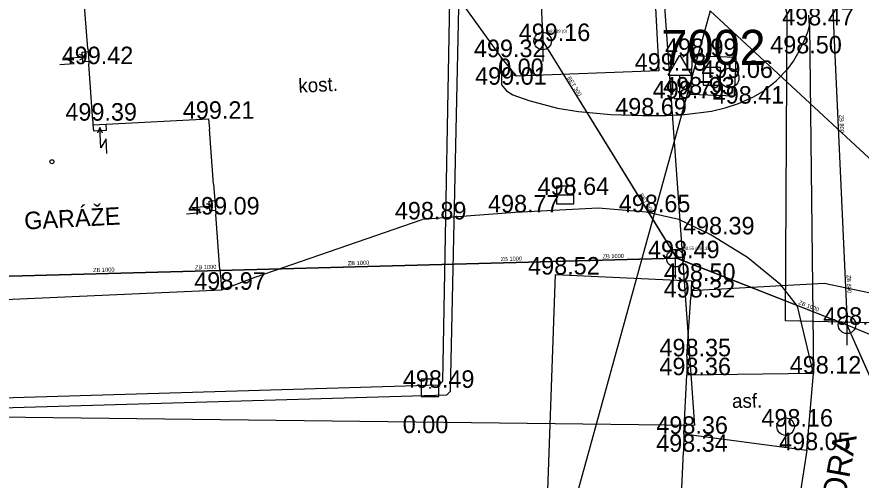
# Model space of a CAD drawing. Extents: x -669642 to -669119, y -1131006 to -1130466.
# Drawn here: x -669604.18 to -669567.99, y -1130599.43 to -1130579.6 of the extents above; entities that cross this region are included whole.
import ezdxf

# ---------------------------------------------------------------- set-up
doc = ezdxf.new("R2010")
doc.units = 0
for name, color, linetype in [('G_Bod_tecka', 7, 'Continuous'), ('G_Bod_vyska', 7, 'Continuous'), ('G_Bodove_pole', 7, 'Continuous'), ('G_Budovy-znacky', 7, 'Continuous'), ('G_Budovy_Objekty', 7, 'Continuous'), ('G_Budovy_vstupy', 7, 'Continuous'), ('G_Cesty_Schody', 7, 'Continuous'), ('G_Objekty_dopravni', 7, 'Continuous'), ('G_Plochy_zpevnene', 7, 'Continuous'), ('G_Popisy_Nazvy', 7, 'Continuous'), ('G_Popisy_objektu', 7, 'Continuous'), ('G_Popisy_povrchu', 7, 'Continuous'), ('G_Site-kanalizace', 7, 'Continuous'), ('G_Site-Rozvadece', 7, 'Continuous'), ('G_Site-Sachty_N', 7, 'Continuous'), ('G_Z_CHRANICKA-TEPLOVOD_kotovane', 7, 'Continuous'), ('G_Z_CHRANICKA-TEPLOVOD_zahozene', 7, 'Continuous'), ('G_Z_ELsilove_podz_kotovane', 7, 'Continuous'), ('G_Z_KANAL_podz_kotovane', 7, 'Continuous'), ('G_Z_SPOJE_nadz_kotovane', 7, 'Continuous'), ('Vrstva 10', 7, 'Continuous'), ('Vrstva 12', 7, 'Continuous'), ('Vrstva 13', 7, 'Continuous'), ('Vrstva 2', 7, 'Continuous'), ('Vrstva 3', 7, 'Continuous'), ('Vrstva 8', 7, 'Continuous')]:
    doc.layers.add(name, color=color, linetype=linetype)

msp = doc.modelspace()

# ---------------------------------------------------------------- linework, layer by layer
at = {"layer": 'G_Bod_tecka'}
for p, q in [((-669570.21, -1130579.96), (-669570.21, -1130579.96)), ((-669581.64, -1130580.63), (-669581.64, -1130580.63)), ((-669583.42, -1130581.32), (-669583.42, -1130581.32)), ((-669575.23, -1130581.27), (-669575.23, -1130581.27)), ((-669570.7, -1130581.16), (-669570.7, -1130581.16)), ((-669601.09, -1130581.62), (-669601.09, -1130581.62)), ((-669576.67, -1130581.9), (-669576.67, -1130581.9)), ((-669582.77, -1130582.13), (-669582.77, -1130582.13)), ((-669573.64, -1130582.21), (-669573.64, -1130582.21)), ((-669583.41, -1130582.5), (-669583.41, -1130582.5)), ((-669575.76, -1130583.09), (-669575.76, -1130583.09)), ((-669575.31, -1130582.92), (-669575.31, -1130582.92)), ((-669573.25, -1130583.31), (-669573.25, -1130583.31)), ((-669577.35, -1130583.82), (-669577.35, -1130583.82)), ((-669600.93, -1130584.04), (-669600.93, -1130584.04)), ((-669595.96, -1130583.96), (-669595.96, -1130583.96)), ((-669580.68, -1130587.22), (-669580.68, -1130587.22)), ((-669595.65, -1130588.06), (-669595.65, -1130588.06)), ((-669582.82, -1130587.97), (-669582.82, -1130587.97)), ((-669577.2, -1130587.96), (-669577.2, -1130587.96)), ((-669586.81, -1130588.27), (-669586.81, -1130588.27)), ((-669574.46, -1130588.91), (-669574.46, -1130588.91)), ((-669575.96, -1130589.93), (-669575.96, -1130589.93)), ((-669581.1, -1130590.63), (-669581.1, -1130590.63)), ((-669575.26, -1130590.9), (-669575.26, -1130590.9)), ((-669595.41, -1130591.28), (-669595.41, -1130591.28)), ((-669575.29, -1130591.61), (-669575.29, -1130591.61)), ((-669568.6, -1130592.78), (-669568.6, -1130592.78)), ((-669575.47, -1130594.13), (-669575.47, -1130594.13)), ((-669575.46, -1130594.94), (-669575.46, -1130594.94)), ((-669570.03, -1130594.87), (-669570.03, -1130594.87)), ((-669586.47, -1130595.48), (-669586.47, -1130595.48)), ((-669571.23, -1130597.14), (-669571.23, -1130597.14)), ((-669586.86, -1130597.42), (-669586.86, -1130597.42)), ((-669575.59, -1130597.45), (-669575.59, -1130597.45)), ((-669575.61, -1130598.22), (-669575.61, -1130598.22)), ((-669570.32, -1130598.15), (-669570.32, -1130598.15))]:
    msp.add_line(p, q, dxfattribs=at)
at = {"layer": 'G_Bodove_pole'}
for radius in [0.412, 0.05]:
    msp.add_circle((-669573.64, -1130582.21), radius, dxfattribs=at)
at = {"layer": 'G_Budovy-znacky'}
msp.add_circle((-669602.679, -1130585.8), 0.0875, dxfattribs=at)
at = {"layer": 'G_Budovy_Objekty'}
for p, q in [((-669601.14, -1130580.95), (-669601.13, -1130581.08)), ((-669601.13, -1130581.08), (-669601.1, -1130581.5)), ((-669601.1, -1130581.5), (-669601.09, -1130581.62)), ((-669600.93, -1130584.04), (-669600.92, -1130584.22)), ((-669600.92, -1130584.22), (-669600.35, -1130584.19)), ((-669600.35, -1130584.19), (-669595.96, -1130583.96)), ((-669595.96, -1130583.96), (-669595.93, -1130584.4)), ((-669595.75, -1130586.76), (-669595.7, -1130587.46)), ((-669595.7, -1130587.46), (-669595.66, -1130587.89)), ((-669595.66, -1130587.89), (-669595.65, -1130588.06)), ((-669595.48, -1130590.41), (-669595.44, -1130590.84)), ((-669581.1, -1130590.63), (-669581.86, -1130611.31)), ((-669581.1, -1130590.63), (-669575.26, -1130590.9)), ((-669595.44, -1130590.84), (-669595.41, -1130591.28)), ((-669575.26, -1130590.9), (-669575.29, -1130591.61)), ((-669606.39, -1130591.78), (-669595.41, -1130591.28)), ((-669575.47, -1130594.13), (-669575.46, -1130594.94)), ((-669575.59, -1130597.45), (-669575.61, -1130598.22))]:
    msp.add_line(p, q, dxfattribs=at)
at = {"layer": 'G_Budovy_vstupy'}
for p, q in [((-669601.14, -1130580.95), (-669601.33, -1130578.53)), ((-669600.93, -1130584.04), (-669601.09, -1130581.62)), ((-669595.75, -1130586.76), (-669595.93, -1130584.4)), ((-669595.48, -1130590.41), (-669595.65, -1130588.06))]:
    msp.add_line(p, q, dxfattribs=at)
for points in [[(-669575.47, -1130594.13), (-669575.29, -1130591.61)], [(-669575.59, -1130597.45), (-669575.46, -1130594.94)], [(-669575.72, -1130600.72), (-669575.61, -1130598.22)]]:
    msp.add_lwpolyline(points, dxfattribs=at)
at = {"layer": 'G_Cesty_Schody'}
for p, q in [((-669583.42, -1130581.32), (-669586.72, -1130576.72)), ((-669570.21, -1130579.96), (-669570.03, -1130594.87))]:
    msp.add_line(p, q, dxfattribs=at)
at = {"layer": 'G_Objekty_dopravni'}
for p, q in [((-669576.26, -1130582.09), (-669575.76, -1130581.24)), ((-669575.76, -1130581.24), (-669575.26, -1130582.09)), ((-669576.26, -1130582.09), (-669575.26, -1130582.09)), ((-669575.76, -1130583.09), (-669575.76, -1130582.09)), ((-669576.01, -1130583.09), (-669575.51, -1130583.09))]:
    msp.add_line(p, q, dxfattribs=at)
at = {"layer": 'G_Plochy_zpevnene'}
for p, q in [((-669582.77, -1130582.13), (-669583.42, -1130581.32)), ((-669575.23, -1130581.27), (-669575.31, -1130582.92)), ((-669573.36, -1130581.34), (-669575.23, -1130581.27)), ((-669573.36, -1130581.34), (-669573.44, -1130582.99)), ((-669576.67, -1130581.9), (-669582.77, -1130582.13)), ((-669573.44, -1130582.99), (-669575.31, -1130582.92)), ((-669593.97, -1130590.74), (-669586.81, -1130588.27)), ((-669595.41, -1130591.28), (-669593.97, -1130590.74)), ((-669570.03, -1130594.87), (-669575.46, -1130594.94)), ((-669570.32, -1130598.15), (-669570.03, -1130594.87)), ((-669575.59, -1130597.45), (-669570.32, -1130598.15)), ((-669570.32, -1130598.15), (-669571.91, -1130608.61))]:
    msp.add_line(p, q, dxfattribs=at)
for points in [[(-669577.93, -1130558.05), (-669577.32, -1130569.5), (-669576.67, -1130581.9)], [(-669583.42, -1130581.32), (-669583.41, -1130582.5), (-669583.2, -1130582.76), (-669582.92, -1130582.93), (-669582.23, -1130583.18), (-669581.01, -1130583.5), (-669580.1, -1130583.65), (-669578.72, -1130583.78), (-669577.35, -1130583.82), (-669576.33, -1130583.82), (-669575.56, -1130583.78), (-669574.4, -1130583.63), (-669573.82, -1130583.49), (-669573.25, -1130583.31), (-669572.64, -1130583.04), (-669572.21, -1130582.79), (-669571.63, -1130582.34), (-669571.12, -1130581.8), (-669570.89, -1130581.49), (-669570.7, -1130581.16), (-669570.47, -1130580.69), (-669570.27, -1130580.21), (-669570.21, -1130579.96), (-669570.23, -1130579.52)], [(-669570.03, -1130594.87), (-669570.72, -1130591.98), (-669571.43, -1130591.07), (-669572.86, -1130589.9), (-669574.46, -1130588.91), (-669575.8, -1130588.27), (-669577.2, -1130587.96), (-669579.27, -1130587.79), (-669582.82, -1130587.97), (-669586.81, -1130588.27)]]:
    msp.add_lwpolyline(points, dxfattribs=at)
at = {"layer": 'G_Site-kanalizace'}
for p, q in [((-669581.64, -1130580.255), (-669581.64, -1130581.505)), ((-669581.055, -1130587.22), (-669580.305, -1130587.22)), ((-669575.96, -1130589.555), (-669575.96, -1130590.805)), ((-669568.6, -1130592.405), (-669568.6, -1130593.655)), ((-669571.23, -1130596.765), (-669571.23, -1130598.015))]:
    msp.add_line(p, q, dxfattribs=at)
msp.add_lwpolyline([(-669581.055, -1130587.594), (-669580.305, -1130587.594), (-669580.305, -1130586.844), (-669581.055, -1130586.844)], close=True, dxfattribs=at)
for centre in [(-669581.64, -1130580.63), (-669575.96, -1130589.93), (-669568.6, -1130592.78), (-669571.23, -1130597.14)]:
    msp.add_circle(centre, 0.375, dxfattribs=at)
at = {"layer": 'G_Site-Rozvadece'}
for p, q in [((-669602.113, -1130581.367), (-669601.24, -1130581.3)), ((-669601.719, -1130581.588), (-669602.113, -1130581.367)), ((-669601.24, -1130581.3), (-669601.493, -1130581.209)), ((-669601.476, -1130581.428), (-669601.24, -1130581.3)), ((-669601.38, -1130581.1), (-669601.13, -1130581.08)), ((-669601.35, -1130581.52), (-669601.38, -1130581.1)), ((-669602.343, -1130581.636), (-669601.719, -1130581.588)), ((-669601.1, -1130581.5), (-669601.35, -1130581.52)), ((-669600.92, -1130584.22), (-669600.9, -1130584.47)), ((-669600.34, -1130584.44), (-669600.35, -1130584.19)), ((-669600.9, -1130584.47), (-669600.34, -1130584.44)), ((-669600.63, -1130584.33), (-669600.727, -1130584.581)), ((-669600.584, -1130585.204), (-669600.63, -1130584.33)), ((-669600.507, -1130584.569), (-669600.63, -1130584.33)), ((-669600.354, -1130584.816), (-669600.584, -1130585.204)), ((-669600.321, -1130585.441), (-669600.354, -1130584.816)), ((-669595.94, -1130587.48), (-669595.7, -1130587.46)), ((-669595.91, -1130587.91), (-669595.94, -1130587.48)), ((-669596.672, -1130587.755), (-669595.8, -1130587.69)), ((-669596.279, -1130587.977), (-669596.672, -1130587.755)), ((-669595.8, -1130587.69), (-669596.052, -1130587.598)), ((-669596.036, -1130587.818), (-669595.8, -1130587.69)), ((-669596.904, -1130588.024), (-669596.279, -1130587.977)), ((-669595.66, -1130587.89), (-669595.91, -1130587.91))]:
    msp.add_line(p, q, dxfattribs=at)
at = {"layer": 'G_Site-Sachty_N'}
for points in [[(-669574.765, -1130582.515), (-669574.015, -1130582.515), (-669574.015, -1130581.765), (-669574.765, -1130581.765)], [(-669586.845, -1130595.855), (-669586.095, -1130595.855), (-669586.095, -1130595.105), (-669586.845, -1130595.105)]]:
    msp.add_lwpolyline(points, close=True, dxfattribs=at)
for centre in [(-669574.39, -1130582.14), (-669586.47, -1130595.48)]:
    msp.add_circle(centre, 0.02, dxfattribs=at)
at = {"layer": 'G_Z_CHRANICKA-TEPLOVOD_kotovane'}
for points in [[(-669530.86, -1130536.09), (-669531.69, -1130536.11), (-669538.05, -1130536.01), (-669551.6, -1130535.98), (-669556.47, -1130536.1), (-669556.55, -1130536.06), (-669560.64, -1130536.09), (-669574.53, -1130536.2), (-669574.67, -1130536.36), (-669574.72, -1130541.62), (-669574.88, -1130541.76), (-669582.24, -1130541.63), (-669583.55, -1130541.58), (-669583.7, -1130541.72), (-669584.58, -1130558.61), (-669585.58, -1130575.76), (-669585.93, -1130595.21), (-669586.1, -1130595.37), (-669614.44, -1130596.21), (-669640.046, -1130597.079)], [(-669640.046, -1130597.497), (-669614.65, -1130596.62), (-669585.75, -1130595.78), (-669585.6, -1130595.63), (-669585.16, -1130575.89), (-669584.28, -1130558.61), (-669583.35, -1130542.15), (-669583.19, -1130542.01), (-669581.88, -1130542.11), (-669574.53, -1130542.49), (-669574.36, -1130542.36), (-669574.15, -1130537.08), (-669574.02, -1130536.91), (-669560.19, -1130536.48), (-669556.56, -1130536.39), (-669556.35, -1130536.38), (-669551.53, -1130536.3), (-669538.03, -1130536.37), (-669531.82, -1130536.43), (-669530.95, -1130536.44)]]:
    msp.add_lwpolyline(points, dxfattribs=at)
at = {"layer": 'G_Z_CHRANICKA-TEPLOVOD_zahozene'}
for p, q in [((-669579.45, -1130537.33), (-669575.13, -1130597.1)), ((-669575.13, -1130597.1), (-669640.046, -1130596.308))]:
    msp.add_line(p, q, dxfattribs=at)
at = {"layer": 'G_Z_ELsilove_podz_kotovane'}
for points in [[(-669500.66, -1130540.32), (-669515.72, -1130539.79), (-669523.73, -1130540.47), (-669527.21, -1130540.62), (-669526.83, -1130552.4), (-669536.59, -1130554.49), (-669535.34, -1130593.45), (-669571.24, -1130592.61), (-669571.16, -1130579.46), (-669571.39, -1130578.6), (-669571.77, -1130566.09), (-669572.17, -1130554.22), (-669572.49, -1130545.57), (-669573.36, -1130532.75), (-669573.82, -1130523.78), (-669573.87, -1130520.47), (-669574.25, -1130510), (-669574.87, -1130499.19), (-669574.76, -1130498.82), (-669574.94, -1130498.48), (-669574.995, -1130497.207)], [(-669562.603, -1130591.65), (-669562.643, -1130591.795), (-669562.768, -1130591.942), (-669562.792, -1130591.97), (-669562.909, -1130592.074), (-669563.141, -1130592.109), (-669563.708, -1130592.194), (-669563.827, -1130592.212), (-669563.839, -1130592.214), (-669569.578, -1130591.012), (-669575.276, -1130591.327)]]:
    msp.add_lwpolyline(points, dxfattribs=at)
at = {"layer": 'G_Z_KANAL_podz_kotovane'}
for p, q in [((-669582.19, -1130568.03), (-669581.64, -1130580.63)), ((-669581.64, -1130580.63), (-669575.91, -1130589.92)), ((-669640.046, -1130591.644), (-669575.91, -1130589.92)), ((-669575.91, -1130589.92), (-669568.6, -1130592.78)), ((-669568.6, -1130592.78), (-669532.28, -1130607.88)), ((-669568.6, -1130592.78), (-669555.25, -1130623.02))]:
    msp.add_line(p, q, dxfattribs=at)
msp.add_lwpolyline([(-669571.27, -1130529.5), (-669571.46, -1130530.2), (-669568.6, -1130592.41), (-669568.59, -1130592.79)], dxfattribs=at)
at = {"layer": 'G_Z_SPOJE_nadz_kotovane'}
for points in [[(-669574.46, -1130579.33), (-669583.02, -1130610.35)], [(-669574.46, -1130579.33), (-669563.01, -1130589.94)]]:
    msp.add_lwpolyline(points, dxfattribs=at)
at = {"layer": 'Vrstva 10'}
msp.add_lwpolyline([(-669571.274, -1130529.495), (-669571.46, -1130530.195), (-669568.603, -1130592.41), (-669568.585, -1130592.792)], dxfattribs=at)
at = {"layer": 'Vrstva 12'}
for p, q in [((-669640.046, -1130591.649), (-669575.912, -1130589.924)), ((-669575.912, -1130589.924), (-669568.603, -1130592.785)), ((-669568.603, -1130592.785), (-669532.275, -1130607.883))]:
    msp.add_line(p, q, dxfattribs=at)
at = {"layer": 'Vrstva 13'}
for p, q in [((-669582.19, -1130568.03), (-669581.635, -1130580.629)), ((-669581.635, -1130580.629), (-669575.912, -1130589.924)), ((-669568.603, -1130592.785), (-669555.249, -1130623.016))]:
    msp.add_line(p, q, dxfattribs=at)
at = {"layer": 'Vrstva 8'}
for p, q in [((-669581.635, -1130580.629), (-669581.635, -1130580.629)), ((-669575.912, -1130589.924), (-669575.912, -1130589.924))]:
    msp.add_line(p, q, dxfattribs=at)

# ---------------------------------------------------------------- texts
at = {"layer": 'G_Bod_vyska'}
for s, p in [('498.47', (-669571.376, -1130579.96)), ('499.16', (-669582.67, -1130580.63)), ('499.32', (-669584.588, -1130581.32)), ('498.99', (-669576.4, -1130581.27)), ('498.50', (-669571.888, -1130581.16)), ('499.42', (-669602.258, -1130581.62)), ('0.00', (-669583.55, -1130582.13)), ('499.13', (-669577.696, -1130581.9)), ('499.06', (-669574.841, -1130582.21)), ('499.01', (-669584.538, -1130582.5)), ('498.79', (-669576.928, -1130583.09)), ('498.93', (-669576.478, -1130582.92)), ('498.41', (-669574.354, -1130583.31)), ('498.69', (-669578.532, -1130583.82)), ('499.39', (-669602.1, -1130584.04)), ('499.21', (-669597.066, -1130583.96)), ('498.64', (-669581.86, -1130587.22)), ('499.09', (-669596.842, -1130588.06)), ('498.89', (-669587.978, -1130588.27)), ('498.77', (-669583.986, -1130587.97)), ('498.65', (-669578.38, -1130587.96)), ('498.39', (-669575.628, -1130588.91)), ('498.49', (-669577.128, -1130589.93)), ('498.52', (-669582.266, -1130590.63)), ('498.50', (-669576.445, -1130590.9)), ('498.97', (-669596.578, -1130591.28)), ('498.32', (-669576.456, -1130591.61)), ('498.13', (-669569.624, -1130592.78)), ('498.35', (-669576.636, -1130594.13)), ('498.36', (-669576.64, -1130594.94)), ('498.12', (-669571.054, -1130594.87)), ('498.49', (-669587.635, -1130595.48)), ('498.16', (-669572.268, -1130597.14)), ('0.00', (-669587.64, -1130597.42)), ('498.36', (-669576.77, -1130597.45)), ('498.34', (-669576.776, -1130598.22)), ('498.05', (-669571.508, -1130598.15))]:
    msp.add_text(s, height=0.75, dxfattribs=at).set_placement(p)
at = {"layer": 'G_Bodove_pole'}
msp.add_text('7002', height=1.5, dxfattribs=at).set_placement((-669576.553, -1130581.65))
at = {"layer": 'G_Popisy_Nazvy'}
msp.add_text('U DVORA', height=1, rotation=79.6652, dxfattribs=at).set_placement((-669569.268, -1130603.544))
at = {"layer": 'G_Popisy_objektu'}
msp.add_text('GARÁŽE', height=0.75, rotation=3.061, dxfattribs=at).set_placement((-669603.846, -1130588.705))
at = {"layer": 'G_Popisy_povrchu'}
for s, rotation, p in [('kost.', 2.9669, (-669592.1, -1130582.849)), ('asf.', 0.7386, (-669573.522, -1130596.343))]:
    msp.add_text(s, height=0.6, rotation=rotation, dxfattribs=at).set_placement(p)
at = {"layer": 'Vrstva 2'}
for s, height, p in [('499.39 (0)', 0.1316, (-669581.43, -1130580.276)), ('498.55 (496.38)', 0.13163, (-669575.706, -1130589.571))]:
    msp.add_text(s, height=height, dxfattribs=at).set_placement(p)
at = {"layer": 'Vrstva 3'}
for s, rotation, p in [('BET 300', 301.6254, (-669580.6, -1130582.209)), ('ZB 800', 272.6394, (-669568.928, -1130583.786)), ('BET 300', 301.6254, (-669577.517, -1130587.217)), ('ZB 1000', 1.5682, (-669589.992, -1130590.232)), ('ZB 1000', 1.5356, (-669583.441, -1130590.056)), ('ZB 1000', 1.5174, (-669579.073, -1130589.939)), ('ZB 1000', 1.5174, (-669600.909, -1130590.526)), ('ZB 1000', 1.5347, (-669596.543, -1130590.409)), ('ZB 800', 272.597, (-669568.613, -1130590.644)), ('ZB 1000', 338.6406, (-669570.693, -1130591.891))]:
    msp.add_text(s, height=0.1755, rotation=rotation, dxfattribs=at).set_placement(p)

doc.saveas('drawing.dxf')
